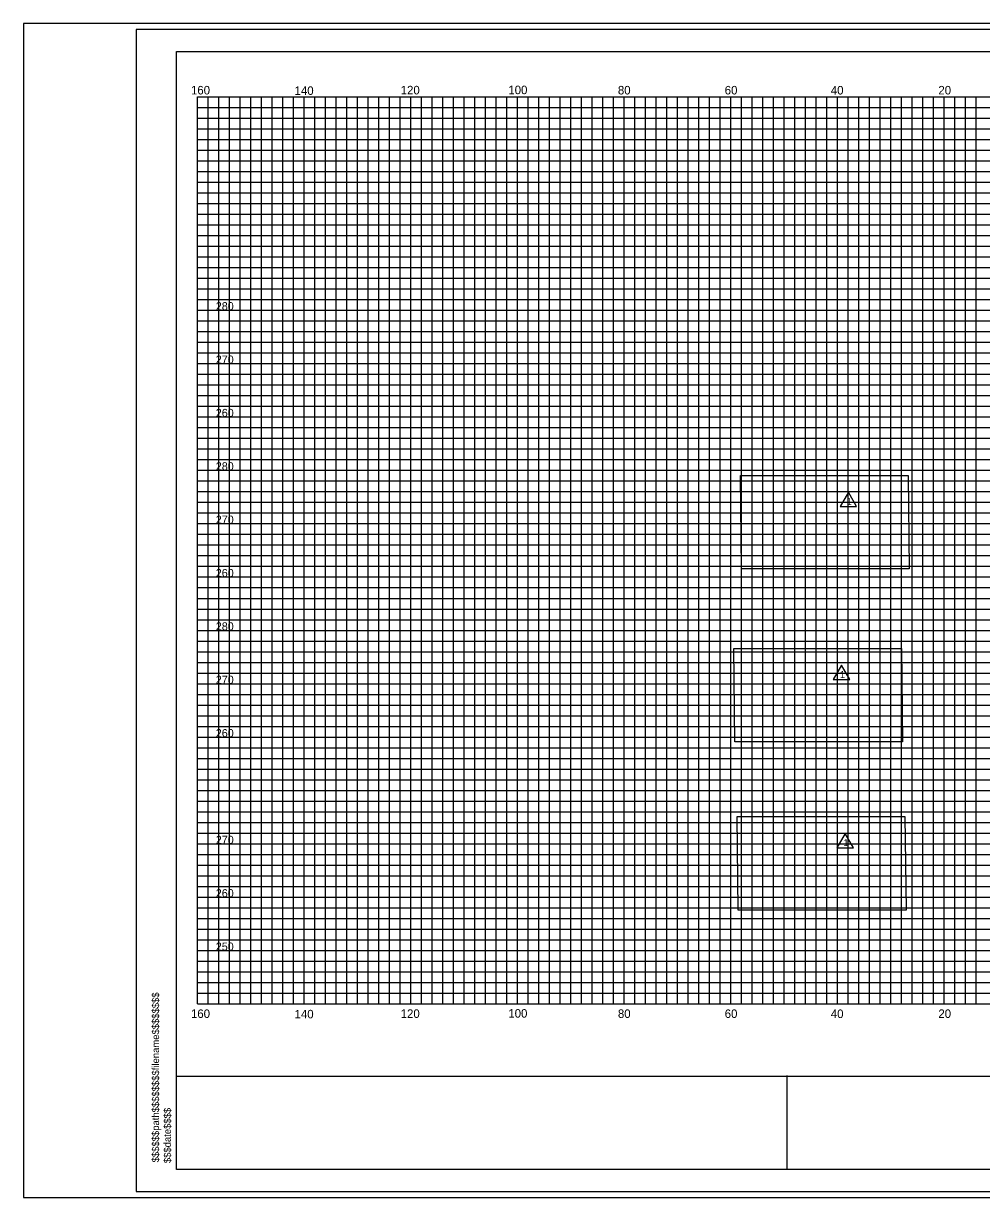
# Model space of a CAD drawing. Extents: x 967 to 1326, y 964 to 3704.
# Drawn here: x 967.4 to 1147, y 1523.7 to 1743.7 of the extents above; entities that cross this region are included whole.
import ezdxf

# ---------------------------------------------------------------- set-up
doc = ezdxf.new("R2010")
doc.units = 0
for name, color, linetype in [('Default', 7, 'Continuous'), ('RD_SHT_Bndy', 7, 'Continuous'), ('RD_SHT_IplotShp', 7, 'Continuous'), ('RD_SHT_MjGrid', 7, 'Continuous'), ('RD_SHT_MnGrid', 7, 'Continuous'), ('RD_SHT_TX', 7, 'Continuous'), ('RD_XS_TX_Station', 7, 'Continuous')]:
    doc.layers.add(name, color=color, linetype=linetype)

msp = doc.modelspace()

# ---------------------------------------------------------------- linework, layer by layer
at = {"layer": 'RD_SHT_Bndy'}
for p, q in [((996.11, 1528.98), (996.11, 1738.46)), ((996.11, 1738.46), (1323.89, 1738.46)), ((996.11, 1546.49), (1323.89, 1546.49)), ((1110.59, 1528.98), (1110.59, 1546.56)), ((1323.89, 1528.98), (996.11, 1528.98))]:
    msp.add_line(p, q, dxfattribs=at)
at = {"layer": 'RD_SHT_IplotShp'}
for points in [[(967.41, 1523.72), (1326.28, 1523.72), (1326.28, 1743.72), (967.41, 1743.72)], [(988.52, 1524.84), (1326.28, 1524.84), (1326.28, 1742.6), (988.52, 1742.6)]]:
    msp.add_lwpolyline(points, close=True, dxfattribs=at)
at = {"layer": 'RD_SHT_MjGrid'}
for p, q in [((1000, 1730), (1320, 1730)), ((1000, 1560), (1000, 1730)), ((1010, 1560), (1010, 1730)), ((1020, 1560), (1020, 1730)), ((1030, 1560), (1030, 1730)), ((1040, 1560), (1040, 1730)), ((1050, 1560), (1050, 1730)), ((1060, 1560), (1060, 1730)), ((1070, 1560), (1070, 1730)), ((1080, 1560), (1080, 1730)), ((1090, 1560), (1090, 1730)), ((1100, 1560), (1100, 1730)), ((1110, 1560), (1110, 1730)), ((1120, 1560), (1120, 1730)), ((1130, 1560), (1130, 1730)), ((1140, 1560), (1140, 1730)), ((1000, 1720), (1320, 1720)), ((1000, 1710), (1320, 1710)), ((1000, 1700), (1320, 1700)), ((1000, 1690), (1320, 1690)), ((1000, 1680), (1320, 1680)), ((1000, 1670), (1320, 1670)), ((1000, 1660), (1320, 1660)), ((1000, 1650), (1320, 1650)), ((1000, 1640), (1320, 1640)), ((1000, 1630), (1320, 1630)), ((1000, 1620), (1320, 1620)), ((1000, 1610), (1320, 1610)), ((1000, 1600), (1320, 1600)), ((1000, 1590), (1320, 1590)), ((1000, 1580), (1320, 1580)), ((1000, 1570), (1320, 1570)), ((1000, 1560), (1320, 1560))]:
    msp.add_line(p, q, dxfattribs=at)
at = {"layer": 'RD_SHT_MnGrid'}
for p, q in [((1002, 1560), (1002, 1730)), ((1004, 1560), (1004, 1730)), ((1006, 1560), (1006, 1730)), ((1008, 1560), (1008, 1730)), ((1012, 1560), (1012, 1730)), ((1014, 1560), (1014, 1730)), ((1016, 1560), (1016, 1730)), ((1018, 1560), (1018, 1730)), ((1022, 1560), (1022, 1730)), ((1024, 1560), (1024, 1730)), ((1026, 1560), (1026, 1730)), ((1028, 1560), (1028, 1730)), ((1032, 1560), (1032, 1730)), ((1034, 1560), (1034, 1730)), ((1036, 1560), (1036, 1730)), ((1038, 1560), (1038, 1730)), ((1042, 1560), (1042, 1730)), ((1044, 1560), (1044, 1730)), ((1046, 1560), (1046, 1730)), ((1048, 1560), (1048, 1730)), ((1052, 1560), (1052, 1730)), ((1054, 1560), (1054, 1730)), ((1056, 1560), (1056, 1730)), ((1058, 1560), (1058, 1730)), ((1062, 1560), (1062, 1730)), ((1064, 1560), (1064, 1730)), ((1066, 1560), (1066, 1730)), ((1068, 1560), (1068, 1730)), ((1072, 1560), (1072, 1730)), ((1074, 1560), (1074, 1730)), ((1076, 1560), (1076, 1730)), ((1078, 1560), (1078, 1730)), ((1082, 1560), (1082, 1730)), ((1084, 1560), (1084, 1730)), ((1086, 1560), (1086, 1730)), ((1088, 1560), (1088, 1730)), ((1092, 1560), (1092, 1730)), ((1094, 1560), (1094, 1730)), ((1096, 1560), (1096, 1730)), ((1098, 1560), (1098, 1730)), ((1102, 1560), (1102, 1730)), ((1104, 1560), (1104, 1730)), ((1106, 1560), (1106, 1730)), ((1108, 1560), (1108, 1730)), ((1112, 1560), (1112, 1730)), ((1114, 1560), (1114, 1730)), ((1116, 1560), (1116, 1730)), ((1118, 1560), (1118, 1730)), ((1122, 1560), (1122, 1730)), ((1124, 1560), (1124, 1730)), ((1126, 1560), (1126, 1730)), ((1128, 1560), (1128, 1730)), ((1132, 1560), (1132, 1730)), ((1134, 1560), (1134, 1730)), ((1136, 1560), (1136, 1730)), ((1138, 1560), (1138, 1730)), ((1142, 1560), (1142, 1730)), ((1144, 1560), (1144, 1730)), ((1146, 1560), (1146, 1730)), ((1000, 1728), (1320, 1728)), ((1000, 1726), (1320, 1726)), ((1000, 1724), (1320, 1724)), ((1000, 1722), (1320, 1722)), ((1000, 1718), (1320, 1718)), ((1000, 1716), (1320, 1716)), ((1000, 1714), (1320, 1714)), ((1000, 1712), (1320, 1712)), ((1000, 1708), (1320, 1708)), ((1000, 1706), (1320, 1706)), ((1000, 1704), (1320, 1704)), ((1000, 1702), (1320, 1702)), ((1000, 1698), (1320, 1698)), ((1000, 1696), (1320, 1696)), ((1000, 1694), (1320, 1694)), ((1000, 1692), (1320, 1692)), ((1000, 1688), (1320, 1688)), ((1000, 1686), (1320, 1686)), ((1000, 1684), (1320, 1684)), ((1000, 1682), (1320, 1682)), ((1000, 1678), (1320, 1678)), ((1000, 1676), (1320, 1676)), ((1000, 1674), (1320, 1674)), ((1000, 1672), (1320, 1672)), ((1000, 1668), (1320, 1668)), ((1000, 1666), (1320, 1666)), ((1000, 1664), (1320, 1664)), ((1000, 1662), (1320, 1662)), ((1000, 1658), (1320, 1658)), ((1000, 1656), (1320, 1656)), ((1000, 1654), (1320, 1654)), ((1000, 1652), (1320, 1652)), ((1000, 1648), (1320, 1648)), ((1000, 1646), (1320, 1646)), ((1000, 1644), (1320, 1644)), ((1000, 1642), (1320, 1642)), ((1000, 1638), (1320, 1638)), ((1000, 1636), (1320, 1636)), ((1000, 1634), (1320, 1634)), ((1000, 1632), (1320, 1632)), ((1000, 1628), (1320, 1628)), ((1000, 1626), (1320, 1626)), ((1000, 1624), (1320, 1624)), ((1000, 1622), (1320, 1622)), ((1000, 1618), (1320, 1618)), ((1000, 1616), (1320, 1616)), ((1000, 1614), (1320, 1614)), ((1000, 1612), (1320, 1612)), ((1000, 1608), (1320, 1608)), ((1000, 1606), (1320, 1606)), ((1000, 1604), (1320, 1604)), ((1000, 1602), (1320, 1602)), ((1000, 1598), (1320, 1598)), ((1000, 1596), (1320, 1596)), ((1000, 1594), (1320, 1594)), ((1000, 1592), (1320, 1592)), ((1000, 1588), (1320, 1588)), ((1000, 1586), (1320, 1586)), ((1000, 1584), (1320, 1584)), ((1000, 1582), (1320, 1582)), ((1000, 1578), (1320, 1578)), ((1000, 1576), (1320, 1576)), ((1000, 1574), (1320, 1574)), ((1000, 1572), (1320, 1572)), ((1000, 1568), (1320, 1568)), ((1000, 1566), (1320, 1566)), ((1000, 1564), (1320, 1564)), ((1000, 1562), (1320, 1562))]:
    msp.add_line(p, q, dxfattribs=at)
at = {"layer": 'RD_SHT_TX'}
for p, q in [((1101.82, 1659.01), (1133.26, 1659.01)), ((1102.02, 1641.5), (1101.82, 1659.01)), ((1133.26, 1659.01), (1133.46, 1641.5)), ((1133.46, 1641.5), (1102.02, 1641.5)), ((1100.54, 1626.6), (1131.98, 1626.6)), ((1100.75, 1609.09), (1100.54, 1626.6)), ((1131.98, 1626.6), (1132.19, 1609.09)), ((1132.19, 1609.09), (1100.75, 1609.09)), ((1101.2, 1595.09), (1132.64, 1595.09)), ((1101.41, 1577.58), (1101.2, 1595.09)), ((1132.64, 1595.09), (1132.85, 1577.58)), ((1132.85, 1577.58), (1101.41, 1577.58))]:
    msp.add_line(p, q, dxfattribs=at)
for points in [[(1123.59, 1653.19), (1122.04, 1655.87), (1120.5, 1653.19)], [(1122.32, 1620.78), (1120.77, 1623.46), (1119.22, 1620.78)], [(1122.98, 1589.27), (1121.43, 1591.95), (1119.88, 1589.27)]]:
    msp.add_lwpolyline(points, close=True, dxfattribs=at)
at = {"layer": 'RD_XS_TX_Station'}
msp.add_lwpolyline([(967.41, 1523.72), (1326.28, 1523.72), (1326.28, 1743.72), (967.41, 1743.72)], close=True, dxfattribs=at)

# ---------------------------------------------------------------- texts
at = {"layer": 'Default'}
for s, p in [('280', (1003.47, 1690)), ('270', (1003.47, 1680)), ('260', (1003.47, 1670)), ('280', (1003.47, 1660)), ('270', (1003.47, 1650)), ('260', (1003.47, 1640)), ('280', (1003.47, 1630)), ('270', (1003.47, 1620)), ('260', (1003.47, 1610)), ('270', (1003.47, 1590)), ('260', (1003.47, 1580)), ('250', (1003.47, 1570))]:
    msp.add_text(s, height=1.5, dxfattribs=at).set_placement(p)
for s, p in [('$$$$$$path$$$$$$$$filename$$$$$$$$', (992.83, 1530.31)), ('$$$date$$$$', (995.04, 1530.17))]:
    msp.add_text(s, height=1.3258, rotation=90, dxfattribs=at).set_placement(p)
at = {"layer": 'RD_SHT_TX'}
for s, height, p in [('160', 1.6, (998.81, 1730.42)), ('140', 1.6, (1018.23, 1730.34)), ('120', 1.6, (1038.12, 1730.43)), ('100', 1.6, (1058.3, 1730.47)), ('80', 1.6, (1078.84, 1730.42)), ('60', 1.6, (1098.86, 1730.42)), ('40', 1.6, (1118.75, 1730.41)), ('20', 1.6, (1138.91, 1730.42)), ('1', 1.3, (1121.72, 1653.48)), ('1', 1.3, (1120.45, 1621.07)), ('1', 1.3, (1121.11, 1589.56)), ('160', 1.6, (998.81, 1557.37)), ('140', 1.6, (1018.23, 1557.29)), ('120', 1.6, (1038.12, 1557.38)), ('100', 1.6, (1058.3, 1557.42)), ('80', 1.6, (1078.84, 1557.37)), ('60', 1.6, (1098.86, 1557.37)), ('40', 1.6, (1118.75, 1557.36)), ('20', 1.6, (1138.91, 1557.37))]:
    msp.add_text(s, height=height, dxfattribs=at).set_placement(p)

doc.saveas('drawing.dxf')
